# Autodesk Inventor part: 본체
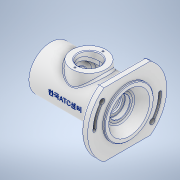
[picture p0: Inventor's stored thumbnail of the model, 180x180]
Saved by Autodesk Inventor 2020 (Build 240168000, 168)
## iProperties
Created: 2022-05
Part Number: 본체
Material: 알루미늄 6061
Document SubType Name: Modeling
Designer: Student
Density: 2.7 g/cm^3
Appearance: 알루미늄 - 평지
Mass: 694.173 g
Surface Area: 619.363 cm^2
Volume: 257.101 cm^3
Author: Student
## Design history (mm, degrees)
sketch "스케치1"
  geometry: L1 (-108.341, 0)-(108.341, 0); L2 (-56, 22.5)-(-48, 22.5); L3 (-48, 22.5)-(-48, 24); L4 (-48, 24)-(-45, 24); L5 (-45, 24)-(-45, 22.5); L6 (-45, 22.5)-(-34, 22.5); L7 (-34, 22.5)-(-34, 17.5); L8 (-34, 17.5)-(-31.75, 17.5); L9 (-31.75, 17.5)-(-31.75, 18.5); L10 (-31.75, 18.5)-(-30, 18.5); L11 (-30, 18.5)-(-30, 17.5); L12 (-30, 17.5)-(-19, 17.5); L13 (-19, 17.5)-(-19, 27); L14 (-19, 27)-(19, 27); L15 (19, 27)-(19, 17.5); L16 (19, 17.5)-(30, 17.5); L17 (30, 17.5)-(30, 15); L18 (30, 15)-(35, 15); L19 (35, 15)-(35, 11); L20 (35, 11)-(37.7, 11); L21 (37.7, 11)-(37.7, 15); L22 (37.7, 15)-(45, 15); L23 (46, 32)-(-56, 32); L24 (-56, 32)-(-56, 22.5); L25 (46, 32)-(46, 58); L26 (46, 58)-(56, 58); L27 (56, 58)-(56, 36); L28 (56, 36)-(59, 36); L29 (59, 36)-(59, 30); L30 (59, 30)-(45, 20); L31 (45, 20)-(45, 15); 3 further points
  constraints: 62 end point, 23 perpendicular, 4 point on line, 2 horizontal, 2 midpoint, 2 vertical, 1 coincident, 1 vertical alignment
  dimensions: "d1" = 45 diameter of L2 L1; "d2" = 48 diameter of L4 L1; "d3" = 45 diameter of L6 L1; "d4" = 35 diameter of L8 L1; "d5" = 37 diameter of L10 L1; "d6" = 54 diameter of L14 L1; "d7" = 30 diameter of L18 L1; "d8" = 22 diameter of L20 L1; "d9" = 30 diameter of L22 L1; "d10" = 64 diameter of L23 L1; "d11" = 8 distance of L2.start L2.end; "d12" = 3 distance of L3.end L4.end; "d13" = 22 distance from line of L6.end L24; "d16" = 1.75 distance of L9.end L10.end; "d17" = 2.25 distance of L7.end L8.end; "d18" = 11 distance of L11.end L12.end; "d19" = 38 distance of L13.end L14.end; "d20" = 11 distance of L15.end L16.end; "d21" = 5 distance of L17.end L18.end; "d22" = 7.3 distance of L21.end L22.end; "d25" = 216.68188 distance of L1.start L1.end; "d26" = 116 diameter of L26 L1; "d27" = 3 distance of L27.end L28.end; "d28" = 13 distance between parallel lines of L29 L25; "d29" = 14 distance between parallel lines of L29 L31; "d30" = 60 diameter of L29.end L1; "d31" = 72 diameter of L28.end L1; "d32" = 115 distance between parallel lines of L29 L24; "d33" = 40 diameter of L30.end L1
revolve "회전1" sketch "스케치1" stored, may be unused: angle "d34" = 90 deg
node "작업 평면1"
sketch "스케치2"
  geometry: C1 r 25 at (0, 0); C2 r 16 at (0, 0); 1 further point
  constraints: 2 centre point, 2 coincident
  dimensions: "d36" = 50 diameter of C1; "d37" = 32 diameter of C2
extrude "돌출1" join sketch "스케치2" stored distance "d38" = 10; taper "d39" = 5 deg; dims "d1" = 45, "d2" = 48, "d3" = 45, "d4" = 35, "d5" = 37, "d6" = 54, "d7" = 30, "d8" = 22, "d9" = 30, "d10" = 64, "d11" = 8, "d12" = 3, "d13" = 22, "d16" = 1.75, "d17" = 2.25, "d18" = 11, "d19" = 38, "d20" = 11, "d21" = 5, "d22" = 7.3, "d25" = 216.68188, "d26" = 116, "d27" = 3, "d28" = 13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
sketch "스케치3"
  geometry: 2 further points
  constraints: 1 other
extrude "돌출2" cut sketch "스케치3" stored distance "d40" = 10; taper "d41" = 0 deg
sketch "스케치4" dims "d42" = 41
  geometry: 3 further points
  constraints: 2 vertical alignment, 1 coincident, 2 other
hole "구멍1" sketch "스케치4" at (0, 20.5) diameter "d43" = 2.459; stored, may be unused: countersink angle "d47" = 90 deg, drill point angle "d49" = 118 deg; dims "d44" = 6, "d45" = 4, "d46" = 2, "d48" = 8
chamfer "모따기1" distance "d53" = 1; stored, may be unused: second distance "d54" = 2, angle "d55" = 45 deg
sketch "스케치5"
  geometry: L1 (-100.618, 47)-(100.618, 47); L2 (100.618, -47)-(-100.618, -47); L3 (-100.618, 47)-(-100.618, 99.417); L4 (-100.618, 99.417)-(100.618, 99.417); L5 (100.618, 99.417)-(100.618, 47); L6 (100.618, -47)-(100.618, -96); L7 (100.618, -96)-(-100.618, -96); L8 (-100.618, -96)-(-100.618, -47); 3 further points
  constraints: 16 end point, 4 perpendicular, 2 midpoint, 2 point on line, 2 vertical alignment, 1 horizontal, 1 parallel, 1 vertical
  dimensions: "d56" = 94 distance between parallel lines of L2 L1; "d57" = 47 distance from line of point (0, 0) L1; "d59" = 90 deg angle of L5 L7; "d60" = 201.23562 distance between parallel lines of L3 L5; "d61" = 52.41734 distance between parallel lines of L4 L1
extrude "돌출3" cut sketch "스케치5" distance "d62" = 10; taper "d63" = 0 deg
sketch "스케치6"
  geometry: L1 (0, 0)-(58, 0); L2 (0, 0)-(36.77, 30.854); L3 (0, 0)-(-36.77, -30.854); A1 r 48 centre (0, 0) between (36.77, 30.854) and (-36.77, -30.854); A2 r 4 centre (36.77, 30.854) between (33.706, 28.283) and (39.834, 33.425); A3 r 4 centre (-36.77, -30.854) between (-39.834, -33.425) and (-32.885, -31.806); A4 r 58 centre (0, 0) between (33.985, -47) and (33.985, 47) reference; A5 r 4 centre (48, 0) between (44, 0) and (52, 0); A6 r 4 centre (-48, 0) between (-44, 0) and (-52, 0); A7 r 52 centre (0, 0) between (-52, 0) and (-39.834, -33.425); A8 r 52 centre (0, 0) between (52, 0) and (39.834, 33.425); A9 r 44 centre (0, 0) between (-44, 0) and (-33.706, -28.283); A10 r 44 centre (0, 0) between (44, 0) and (33.706, 28.283); A11 r 2.25 centre (48, 0) between (45.75, 0) and (50.25, 0); A12 r 2.25 centre (-48, 0) between (-45.75, 0) and (-50.25, 0); A13 r 45.75 centre (0, 0) between (-45.75, 0) and (-32.885, -31.806); A14 r 45.75 centre (0, 0) between (45.75, 0) and (32.885, 31.806); A15 r 50.25 centre (0, 0) between (-50.25, 0) and (-36.233, -34.818); A16 r 50.25 centre (0, 0) between (50.25, 0) and (36.233, 34.818); 6 further points
  constraints: 36 point on circle, 15 centre point, 6 end point, 3 coincident, 2 point on line, 1 horizontal, 1 horizontal alignment
  dimensions: "d64" = 96 diameter of A1; "d65" = 8 diameter of A2; "d66" = 8 diameter of A3; "d67" = 40 deg angle of L1 L2; "d68" = 140 deg angle of L1 L3; "d69" = 8 diameter of A5; "d72" = 8 diameter of A6; "d73" = 52 radius of A7; "d74" = 44 radius of A9; "d75" = 52 radius of A8; "d76" = 44 radius of A10; "d77" = 4.5 diameter of A11; "d78" = 4.5 diameter of A12; "d83" = 50.25 radius of A15; "d84" = 45.75 radius of A13; "d85" = 50.25 radius of A16; "d86" = 45.75 radius of A14
extrude "돌출4" cut sketch "스케치6" extent not by distance; stored distance "d79" = 0; taper "d80" = 0 deg
extrude "돌출5" cut sketch "스케치6" distance "d87" = 4.4; taper "d88" = 0 deg
extrude "돌출6" cut sketch "스케치6" extent not by distance; stored distance "d89" = 0; taper "d90" = 0 deg
node "작업 평면2"
sketch "스케치7"
  geometry: L1 (59, -36)-(59, 36) reference; 3 further points
  constraints: 1 horizontal alignment, 1 midpoint, 1 other
  dimensions: "d92" = 62 distance from line of L1 point (-3, 0)
feature "엠보싱1" sketch "스케치7" dims "d1" = 45, "d2" = 48, "d3" = 45, "d4" = 35, "d5" = 37, "d6" = 54, "d7" = 30, "d8" = 22, "d9" = 30, "d10" = 64, "d11" = 8, "d12" = 3, "d13" = 22, "d16" = 1.75, "d17" = 2.25, "d18" = 11, "d19" = 38, "d20" = 11, "d21" = 5, "d22" = 7.3, "d25" = 216.68188, "d26" = 116, "d27" = 3, "d28" = 13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
feature "스레드1" dims "d95" = 8, "d96" = 0
fillet "모깎기1" dims "d97" = 3
fillet "모깎기2" dims "d98" = 3
chamfer "모따기2" distance "d99" = 1; stored, may be unused: second distance "d100" = 2, angle "d101" = 45 deg
fillet "모깎기3" dims "d102" = 3
fillet "모깎기4" dims "d103" = 0.5
fillet "모깎기5" dims "d104" = 0.6
chamfer "모따기3" distance "d105" = 1; stored, may be unused: second distance "d106" = 2, angle "d107" = 45 deg
chamfer "모따기4" distance "d108" = 0.7; stored, may be unused: second distance "d109" = 2, angle "d110" = 30 deg
fillet "모깎기6" dims "d111" = 3
fillet "모깎기7" dims "d112" = 3
node "솔리드1"
pattern_circular "원형 패턴1" dims angle "d51" = 360 deg
node "투영된 루프1"
feature "A9D066F2-1C7D-4E18-AEED-F7BC21143FA4" dims "d43" = 2.459, "d44" = 6, "d45" = 4, "d46" = 2, "d47" = 90 deg, "d48" = 8, "d49" = 118 deg
other parameters: "d35" = 38, "d70" = 4, "d71" = 4, "d81" = 2.25, "d82" = 2.25, "d91" = 43.25
